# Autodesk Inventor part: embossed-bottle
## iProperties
Shininess: 64.0
Length Units: 11269
Angle Units: 11279
Time Units: 11290
Mass Units: 11283
Length Display Precision: 3
Angle Display Precision: 2
Compacted: True
Part Number: embossed-bottle
Document SubType Name: Modeling
Created: 2002-12
Designer: deepak
Density: 0.0
Volumn: 0.0
Area: 0.0
PropertySet Name: Model Information
Control State: 0
Master: False
Checked Out: False
Author: deepak
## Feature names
1. Revolution1
2. Fillet1
